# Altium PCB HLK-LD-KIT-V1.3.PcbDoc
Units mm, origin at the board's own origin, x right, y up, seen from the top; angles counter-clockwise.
Board outline 37.6 x 27.7 mm, 2 copper layers (Top Layer, Bottom Layer); 27 components, 16 nets, 94 pads, 84 vias.
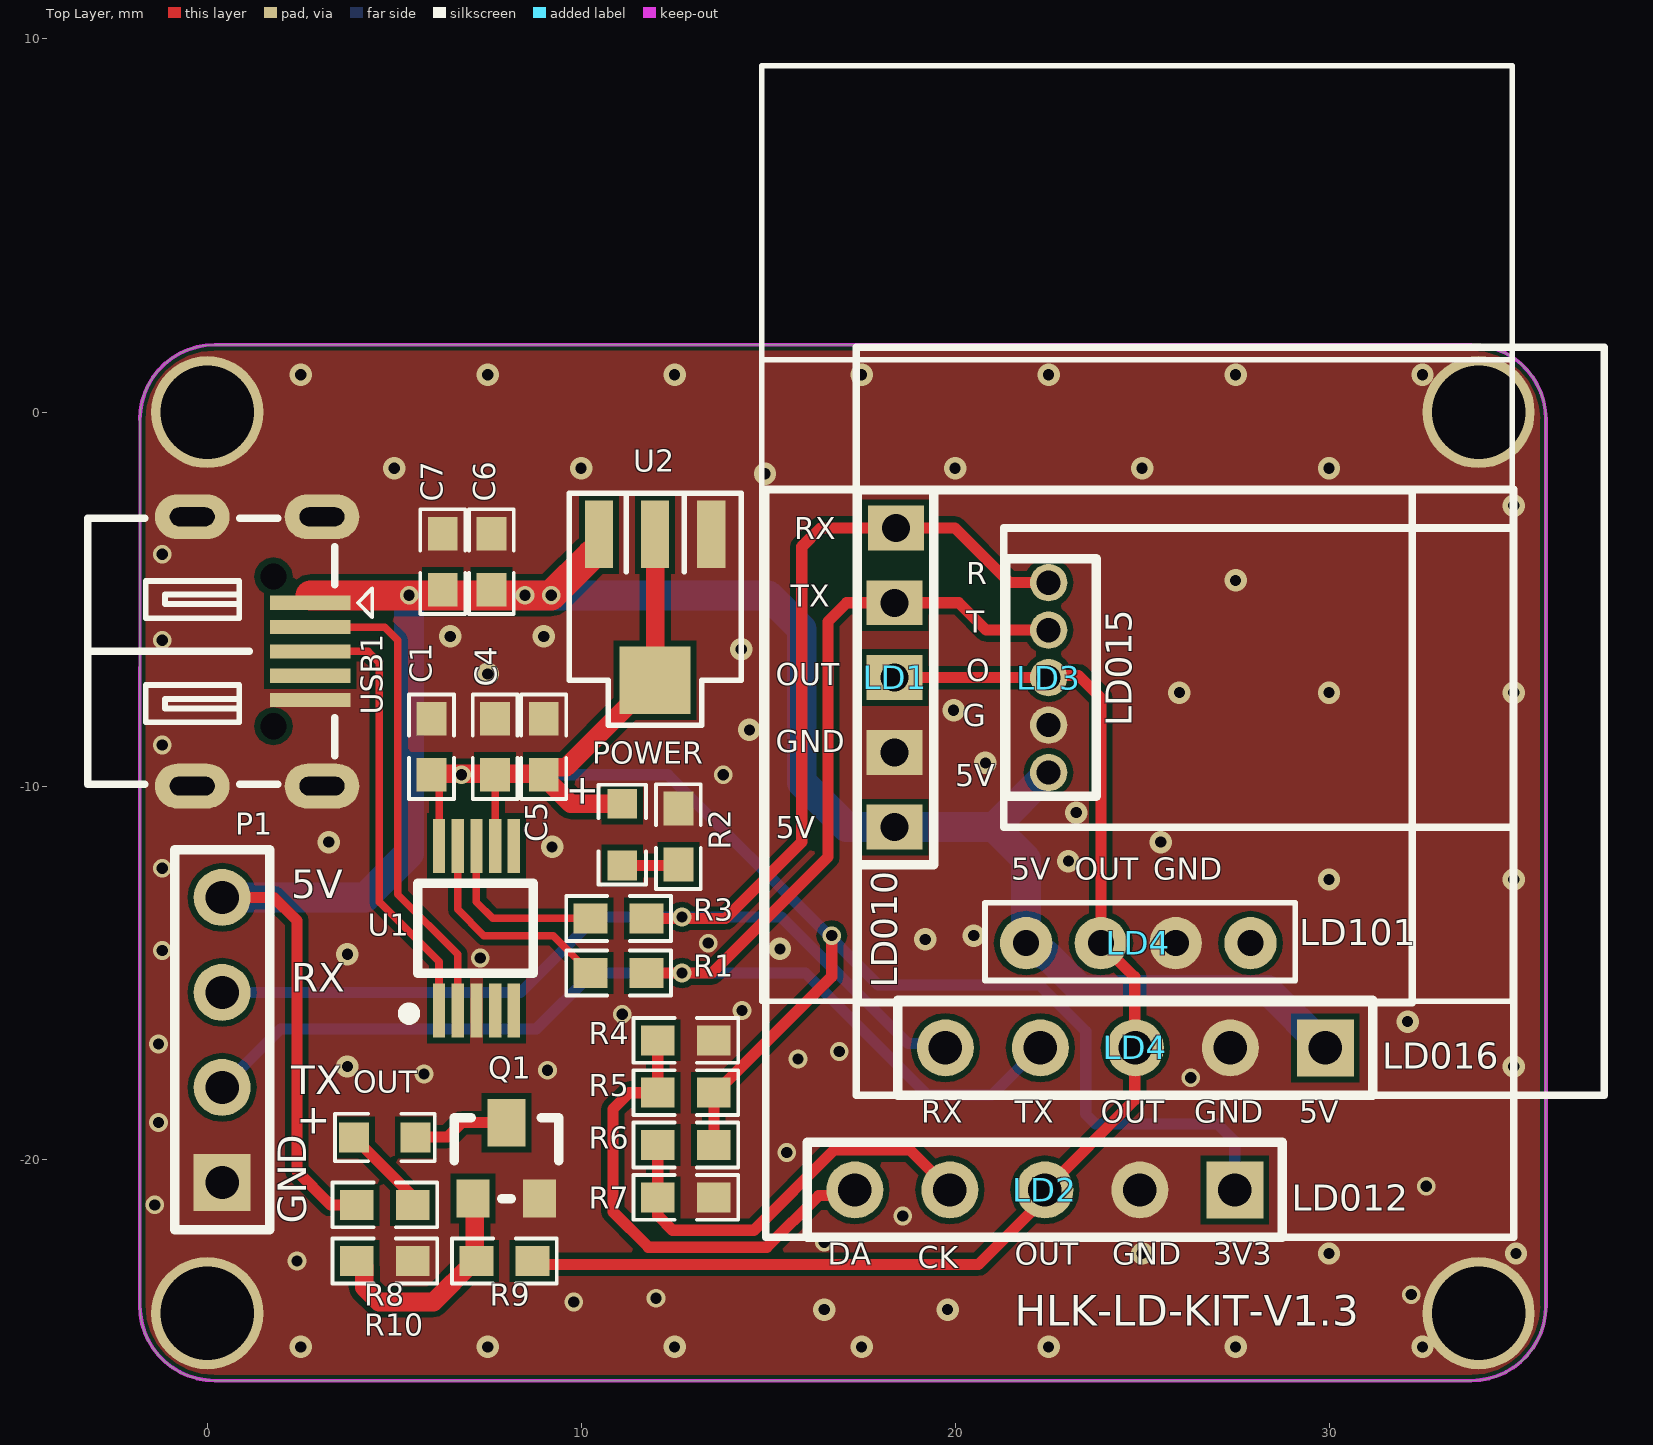
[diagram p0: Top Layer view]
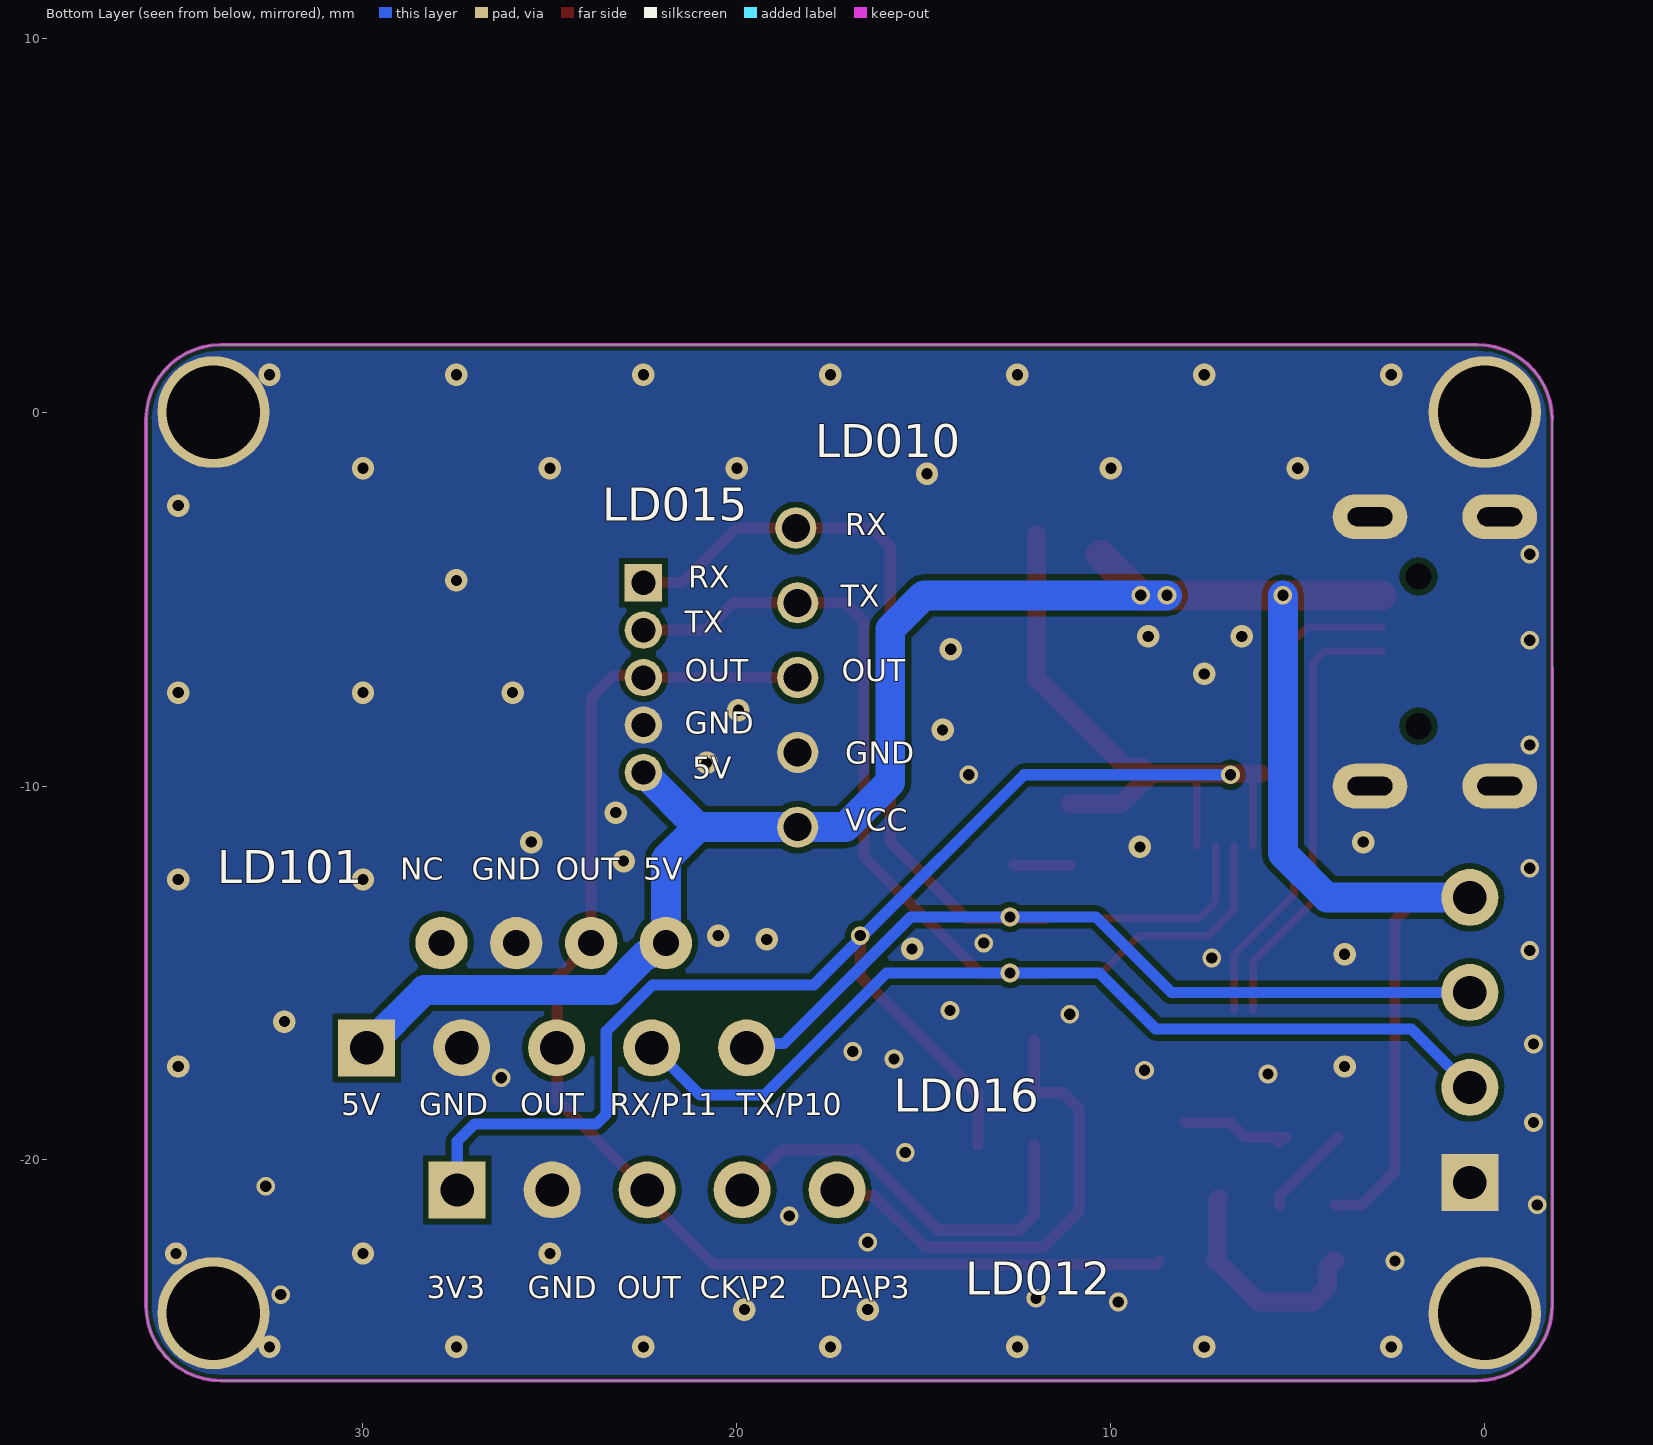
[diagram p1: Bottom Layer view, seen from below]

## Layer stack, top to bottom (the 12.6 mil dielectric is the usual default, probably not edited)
Top Solder: solder mask 0.0102, Solder Resist, Dk 3.5
Top Layer: signal copper 0.0356
Dielectric1: dielectric 0.32, FR-4, Dk 4.8
Bottom Layer: signal copper 0.0356
Bottom Solder: solder mask 0.0102, Solder Resist, Dk 3.5

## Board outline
-1.8,-23.9 -1.8,-0.2 cw(c0.2,-0.2) 0.2,1.8 33.8,1.8 cw(c33.8,-0.2) 35.8,-0.2 35.8,-23.9 cw(c33.8,-23.9) 33.8,-25.9 0.2,-25.9 cw(c0.2,-23.9)

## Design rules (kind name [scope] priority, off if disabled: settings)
Clearance Clearance_1 [OnLayer('Keep-Out Layer')] p1: gap=0.1 ignorepadtopadclearanceinfootprint=FALSE except(0: Arc-Hole Track-Hole SMDPad-Hole THPad-Hole Via-Hole Fill-Hole Poly-Hole Region-Hole Text-Hole)
Clearance [All] p2: gap=0.152 ignorepadtopadclearanceinfootprint=FALSE
FabricationTestPointUsage TestPointUsage [All] p1: valid=0 allowmultiple=FALSE
FabricationTestpoint Testpoint [(IsPad And (OnTopLayer Or OnBottomLayer))] p1: side=3 testpointundercomponent=TRUE minsize=1.016 maxsize=2.54 preferedsize=1.524 minholesize=0 maxholesize=1.016 preferedholesize=0.813 testpointgrid=0.025 allowsidetop=TRUE allowsidebottom=TRUE usegrid=TRUE gridtolerance=0
PolygonConnect [All] p1: connectstyle=Direct reliefconductorwidth=0.254 reliefentries=4 polygonreliefangle="90 Angle" airgapwidth=0.254
RoomDefinition HLK-LD-KIT-V1.3 [InComponentClass('HLK-LD-KIT-V1.3')] p1: confinementstyle=ConfineIn formatcopy=TRUE lockcomponents=FALSE outline -89.208,-91.397 -38.408,-91.397 -38.408,-65.997 -89.208,-65.997
RoutingVias [All] p1: holewidth=0.3 width=0.5 viastyle="Through Hole" minholewidth=0.3 minwidth=0.5 maxholewidth=0.711 maxwidth=1.27
SilkToSolderMaskClearance SilkscreenOverComponentPads [IsPad] p1: minsilkscreentomaskgap=0.254 clearancetoexposedcopper=TRUE
SolderMaskExpansion [All] p1: expansion=0.102 istentingtop=FALSE
Width 5V [InNet('5V')] p1: maxlimit=2 minlimit=0.3 preferedwidth=0.3
Width [All] p2: maxlimit=2 minlimit=0.2 preferedwidth=0.3
27 further rules are at their usual default settings.

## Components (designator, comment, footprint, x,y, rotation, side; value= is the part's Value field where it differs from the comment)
C1 "0.1uF" 0603 6,-8.95 r270 top
C4 "10uF" 0603 7.7,-8.95 r270 top value=100pF
C5 "0.1uF" 0603 9,-8.95 r270 top value=100pF
C6 "10uF" 0603 7.6,-4 r90 top value=100pF
C7 "0.1uF" 0603 6.3,-4 r90 top value=100pF
LD1 "HLK-LD010-5G" HLK-LD010-5G 18.4,-7.1 r0 top locked
LD2 "HLK-LD012-5G" HLK-LD012-5G 22.4,-20.8 r90 top locked
LD3 "HLK-LD015-5G" HLK-LD015-5G 22.5,-7.1 r0 top locked
LD4 "HLK-LD016" HLK-LD012-5G 24.82,-17 r90 top
LD4 "LD101" LD101插座 34.9,-4.2 r180 top (schematic designator U4)
OUT "" 0603LED 4.75,-19.4 r0 top
P1 "2.54*4单排插针" SIP_4P_2.54 0.4,-20.6 r90 top
POWER "LED" 0603LED 11.1,-11.3 r270 top
Q1 "3904" SOT-23 7.111,-21.032 r0 top
R1 "1K" 0603 11,-15 r180 top
R2 "1K" 0603 12.6,-11.35 r90 top
R3 "1K" 0603 11,-13.541 r180 top
R4 "NC/4.7K" 0603 12.8,-16.8 r0 top
R5 "NC/4.7K" 0603 12.8,-18.2 r0 top
R6 "NC/4.7K" 0603 12.8,-19.6 r0 top
R7 "NC/4.7K" 0603 12.8,-21 r0 top
R8 "1K" 0603 4.75,-21.2 r0 top
R9 "4.7K" 0603 7.95,-22.7 r0 top
R10 "47K" 0603 4.75,-22.7 r180 top
U1 "CH340E" MSOP-10 7.2,-13.8 r0 top
U2 "AMS1117" 1117 13.5,-3.2 r180 top
USB1 "micro usb" USB-MICRO_D -0.4,-6.4 r270 top

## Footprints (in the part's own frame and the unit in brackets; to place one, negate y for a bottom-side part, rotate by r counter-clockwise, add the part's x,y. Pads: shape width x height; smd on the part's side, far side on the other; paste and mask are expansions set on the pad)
0603 [mm]
  rect 0.9x0.8 smd: 1(-0.75,0) 2(0.75,0)
  silkscreen extent -1.4,-0.6 1.4,0.6
0603LED [mm]
  rect 0.8x0.8 smd: 1(-0.826,0) 2(0.826,0)
  silkscreen extent -1.33,-0.64 1.33,0.64
1117 [mm]
  rect 1.9x1.8 smd: 0(1.52,3.97)
  rect 0.75x1.8 smd: 1(0.02,0.07) 2(1.52,0.07) 3(3.02,0.07)
  silkscreen extent -0.78,-1.03 3.82,5.17, body extent -0.73,0.14 3.77,4.14, height 1.5
HLK-LD010-5G [mm]
  rect 1.5x1.2 / inner rrect0% 1.2x1.2 / far side round 1.1 hole 0.75: 1(0.025,4) 2(-0.025,2) 3(-0.025,0) 4(-0.025,-2) 5(-0.025,-4)
  silkscreen extent -0.99,-8.7 13.83,5
HLK-LD012-5G [mil]
  round 60 hole 35: 1(0,200) 2(0,100) 3(0,0) 4(0,-100)
  rect 60x60 / inner round 60 / far side rect 60x60 hole 35: 5(0,-200)
  silkscreen extent -50,-494 737,294
HLK-LD015-5G [mm]
  round 1 / inner round 1 / far side rect 1x1 hole 0.65: 1(0,2.54)
  round 1 hole 0.65: 2(0,1.27) 3(0,0) 4(0,-1.27) 5(0,-2.54)
  silkscreen extent -1.2,-4 12.4,4
LD101插座 [mm]
  round 1.4 hole 0.7: 1(13,10) 2(11,10) 3(9,10) 4(7,10)
  silkscreen extent 0,-13.46 20.07,11.56
MSOP-10 [mm]
  rect 0.33x1.45 smd: 1(-1,-2.2) 2(-0.5,-2.2) 3(0,-2.2) 4(0.5,-2.2) 5(1,-2.2) 6(1,2.2) 7(0.5,2.2) 8(0,2.2) 9(-0.5,2.2) 10(-1,2.2)
  silkscreen extent -1.95,-2.44 1.53,1.2
SIP_4P_2.54 [mil]
  rect 60x60 / inner round 60 / far side rect 60x60 hole 35: 1(0,0)
  round 60 hole 35: 2(100,0) 3(200,0) 4(300,0)
  silkscreen extent -50,-50 350,50
SOT-23 [mil]
  rect 35x40 smd: 1(0,0) 2(70,0)
  rect 40x50 smd: 3(35,80)
  silkscreen extent -20,0 90,85
USB-MICRO_D [mm] "micro型USB ，6.7*7.5*2.5mm"
  round 0 hole 0.7 unplated: 0(-2,2.17) 0(2,2.17)
  rect 0.381x2.15 smd: 1(-1.3,3.16) 2(-0.65,3.16) 3(0,3.16) 4(0.65,3.16) 5(1.3,3.16)
  oval 1.2x2 hole 0.5 slot 1.2 at 90 deg: 6(3.6,3.47) 7(3.6,0) 8(-3.6,0) 9(-3.6,3.47)
  silkscreen extent -3.56,-2.79 3.56,4.81

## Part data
C1: library part CAP, "Capacitor"
C4 C5 C6 C7: library part Cap, "Capacitor"
LD4: library part HLK-LD012-5G
OUT: library part LED
P1: library part 2.54*2插针
Q1: library part A09T, "NPN General Purpose Amplifier", PackageDocument=Sep-1998
R1 R2 R3 R4 R5 R6 R7 R8 R9 R10: library part Res1, "Resistor"
U2: library part Component_1
USB1: library part USB-D

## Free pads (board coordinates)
  round 3 hole 2.5: 0(0,-24.1) 0(34,0) 2(0,0) 2(34,-24.1)

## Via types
v1: diameter 0.6, hole 0.3, Top Layer to Bottom Layer, tented both sides, 51 vias
v2: diameter 0.5, hole 0.3, Top Layer to Bottom Layer, tented both sides, 33 vias

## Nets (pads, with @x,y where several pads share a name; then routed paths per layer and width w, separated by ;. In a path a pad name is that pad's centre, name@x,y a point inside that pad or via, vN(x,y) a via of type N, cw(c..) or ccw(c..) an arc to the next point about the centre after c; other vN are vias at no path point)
5V: C6.1 C7.1 LD1.5 LD3.5 LD4.1@21.9,-14.2 LD4.5 P1.4 R8.1 U2.3 USB1.1 | length 63.5
  Top Layer w0.3: P1.4 1.78,-12.98 2.4,-13.6 2.4,-20.3 3.3,-21.2 R8.1
  Top Layer w0.8: 2.76,-4.9 v2(5.4,-4.9) v2(8.5,-4.9) v2(9.2,-4.9) U2.3@10.275,-3.825
  Bottom Layer w0.8: P1.4 4.22,-12.98 5.4,-11.8 v2(5.4,-4.9) ; v2(8.5,-4.9) v2(9.2,-4.9) 15,-4.9 15.9,-5.8 15.9,-9.9 17.1,-11.1 LD1.5 21.04,-11.1 ; LD3.5 21.04,-11.1 ; LD4.5 28.352,-15.452 23.381,-15.452 22.429,-14.5 22.362,-14.5 22.062,-14.2 21.9,-14.2 21.9,-11.96 21.04,-11.1
DM: U1.2 USB1.2 | length 13
  Top Layer w0.2: USB1.2 4.75,-5.75 5.1,-6.1 5.1,-12.9 6.7,-14.5 U1.2
DP: U1.1 USB1.3 | length 11.9
  Top Layer w0.203: USB1.3 4.3,-6.4 4.6,-6.7 4.6,-13.1 6.2,-14.7 U1.1
GND: C1.1 C4.1 C5.1 C6.2 C7.2 LD1.4 LD2.4 LD3.4 LD4.3@25.9,-14.2 LD4.4@27.36,-17 P1.1 pad.0 pad.2 Q1.2 R2.2 R4.2 R7.2 R10.1 U1.3 U2.1 USB1.5 USB1.6 USB1.7 USB1.8 USB1.9
  other v1: 2.5,-25 7.5,-25 12.5,-25 17.5,-25 22.5,-25 27.5,-25 32.5,-25 16.5,-24 19.8,-24 25,-22.5 30,-22.5 35,-22.5 3.75,-17.5 34.94,-17.5 32.1,-16.3 3.75,-14.5 15.315,-14.355 19.2,-14.1 20.5,-14 30,-12.5 34.94,-12.5 23.031,-12.006 9.222,-11.627 3.25,-11.5 25.5,-11.5 23.24,-10.71 20.81,-9.381 14.5,-8.5 19.96,-7.972 26,-7.5 30,-7.5 34.94,-7.5 7.5,-7 14.28,-6.341 6.5,-6 9,-6 27.5,-4.5 34.94,-2.5 14.917,-1.65 5,-1.5 10,-1.5 20,-1.5 25,-1.5 30,-1.5 2.5,1 7.5,1 12.5,1 17.5,1 22.5,1 27.5,1 32.5,1
  other v2: 9.8,-23.8 12,-23.7 32.2,-23.6 2.4,-22.7 16.5,-22.2 18.6,-21.5 -1.4,-21.2 32.6,-20.7 15.5,-19.8 -1.3,-19 26.3,-17.8 5.8,-17.7 9.1,-17.6 15.8,-17.3 16.9,-17.1 -1.3,-16.9 11.1,-16.1 14.3,-16 7.3,-14.6 -1.2,-14.4 13.4,-14.2 -1.2,-12.2 13.8,-9.7 -1.2,-8.9 -1.2,-6.1 -1.2,-3.8
NetLD2_1: LD2.1 R4.1 R5.1 | length 13
  Top Layer w0.3: R4.1 R5.1 11.286,-18.2 10.85,-18.636 10.85,-21.384 11.798,-22.332 14.974,-22.332 16.356,-20.95 17.17,-20.95 LD2.1
NetLD2_2: LD2.2 R6.1 R7.1 | length 11.2
  Top Layer w0.3: R6.1 R7.1 12.05,-21.489 12.44,-21.879 14.621,-21.879 16.764,-19.736 18.796,-19.736 LD2.2
NetOUT_1: OUT.1 R8.2 | length 2.5
  Top Layer w0.3: OUT.1 5.5,-20.976 R8.2
NetOUT_2: OUT.2 Q1.3 | length 2.8
  Top Layer w0.3: OUT.2@5.336,-19.4 OUT.2@5.502,-19.4 ; OUT.2@5.502,-19.512 OUT.2@5.502,-19.474 ; OUT.2 5.592,-19.383 6.425,-19.383 6.809,-19 Q1.3
NetPOWER_2: POWER.2 R2.1 | length 1.5
  Top Layer w0.3: POWER.2 12.575,-12.126 R2.1
NetQ1_1: Q1.1 R9.1 R10.2 | length 6.1
  Top Layer w0.5: R10.2 4.05,-22.7 4.2,-22.85 4.2,-23.407 4.593,-23.8 6.05,-23.8 7.15,-22.7 R9.1 7.156,-22.655 7.156,-21.077 Q1.1
OUT: LD1.3 LD2.3 LD3.3 LD4.2@23.9,-14.2 LD4.3@24.82,-17 R9.2 | length 35
  Top Layer w0.3: R9.2 8.794,-22.794 20.625,-22.794 22.4,-21.019 LD2.3 24.802,-18.398 24.802,-15.102 23.9,-14.2 23.9,-7.647 23.298,-7.045 22.555,-7.045 LD3.3 LD1.3
RX: LD1.1 LD3.1 LD4.1@19.74,-17 P1.3 R3.1 | length 41.9
  Top Layer w0.3: R3.1 13.859,-13.541 15.9,-11.5 15.9,-3.6 16.4,-3.1 LD1.1 20,-3.1 21.46,-4.56 LD3.1
  Bottom Layer w0.3: P1.3 8.38,-15.52 10.4,-13.5 v2(12.7,-13.5) 15.352,-13.5 18.739,-16.887 19.627,-16.887 LD4.1@19.74,-17
RX0_CH340: R1.2 U1.9 | length 6
  Top Layer w0.2: U1.9 6.7,-12.4 6.7,-13.3 7.4,-14 9.25,-14 R1.2
TX: LD1.2 LD3.2 LD4.2@22.28,-17 P1.2 R1.1 | length 43.7
  Top Layer w0.3: R1.1 v2(12.7,-15) 13.5,-15 16.6,-11.9 16.6,-5.6 17.1,-5.1 LD1.2 20.1,-5.1 20.83,-5.83 LD3.2
  Bottom Layer w0.3: P1.2 1.96,-16.5 8.8,-16.5 10.3,-15 v2(12.7,-15) 16,-15 19.264,-18.264 20.986,-18.264 21.865,-17.385 LD4.2@21.865,-17
TX0_CH340: R3.2 U1.8 | length 4.7
  Top Layer w0.2: U1.8 7.2,-13.1 7.641,-13.541 R3.2
V3.3: C1.2 C4.2 C5.2 LD2.5 POWER.1 R5.2 R6.2 U1.7 U1.10 U2.0 U2.2 | length 51.5
  Top Layer w0.2: C1.2 6.2,-9.9 U1.10 ; U1.7 C4.2@7.7,-9.8
  Top Layer w0.3: C4.2 C4.2@7.75,-9.75 ; R6.2 R5.2 13.6,-18.2 16.7,-15.1 v2(16.7,-14)
  Top Layer w0.5: C1.2@6,-9.674 C5.2@9,-9.674 ; POWER.1 9.724,-10.475 9,-9.75 C5.2 C5.2@9,-9.674 ; U2.2 U2.0 11.93,-7.17 9.6,-9.5 9.15,-9.5 9,-9.65 C5.2@9,-9.674
  Bottom Layer w0.3: v2(6.8,-9.7) 12.322,-9.7 16.661,-14.039 17.946,-15.324 22.259,-15.324 23.492,-16.556 23.492,-18.772 23.756,-19.037 27.017,-19.037 27.48,-19.5 LD2.5
pads on no net: LD4.4@27.9,-14.2 U1.4 U1.5 U1.6 USB1.0 USB1.4

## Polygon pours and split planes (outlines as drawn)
GND on Top Layer "Keep-Out Layer-No Net" (solid, remove dead copper, pour order 1000): -2.1,2.2 -2.1,-26 -2.1,-26.6 36.8,-26.6 36.8,2 36.7,2.1 -2,2.1 -2.1,2.2
GND on Bottom Layer "Keep-Out Layer-No Net" (solid, remove dead copper, pour order 1001): -2.1,2.2 -2.1,-26 -2.1,-26.6 36.8,-26.6 36.8,2 36.7,2.1 -2,2.1 -2.1,2.2

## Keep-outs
Keep-Out Layer:
  lines w0.08: -1.8,-6.826 -1.8,-0.2
  lines w0.1: -1.8,-6.826 -1.8,-23.9 ccw(c0.2,-23.9) 0.2,-25.9 33.8,-25.9 ccw(c33.8,-23.9) 35.8,-23.9 35.8,-0.2 ccw(c33.8,-0.2) 33.8,1.8 0.2,1.8 ccw(c0.2,-0.2) -1.8,-0.2

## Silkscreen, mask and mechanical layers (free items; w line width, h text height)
Top Overlay:
  lines w0.15: 14.9,1.4 34.83,1.4 ; 20.8,-15.2 20.8,-13.122 29.1,-13.122 29.1,-15.2 20.8,-15.2
  text "RX" at 15.7,-3.6 h1
  text "R" at 20.3,-4.8 h1
  text "TX" at 15.6,-5.4 h1
  text "T" at 20.3,-6.1 h1
  text "O" at 20.3,-7.4 h1
  text "OUT" at 15.2,-7.5 h1
  text "G" at 20.2,-8.6 h1
  text "GND" at 15.2,-9.3 h1
  text "5V" at 20,-10.2 h1
  text "5V" at 15.2,-11.6 h1
  text "5V" at 21.5,-12.7 h1
  text "OUT" at 23.2,-12.7 h1
  text "GND" at 25.3,-12.7 h1
  text "5V" at 2.25,-13.25 h1.3
  text "LD101" at 29.2,-14.5 h1.2
  text "RX" at 2.25,-15.75 h1.3
  text "TX" at 2.25,-18.5 h1.3
  text "RX" at 19.1,-19.2 h1
  text "TX" at 21.6,-19.2 h1
  text "OUT" at 23.9,-19.2 h1
  text "GND" at 26.4,-19.2 h1
  text "5V" at 29.2,-19.2 h1
  text "GND" at 2.9,-21.7 h1.3 r90
  text "DA" at 16.6,-23 h1
  text "OUT" at 21.6,-23 h1
  text "GND" at 24.2,-23 h1
  text "3V3" at 26.9,-23 h1
  text "CK" at 19,-23.1 h1
  text "HLK-LD-KIT-V1.3" at 21.6,-24.7 h1.4
Bottom Overlay:
  text "LD010" at 17.9,-1.5 h1.5
  text "LD015" at 23.6,-3.2 h1.5
  text "5V" at 22.5,-12.7 h1
  text "OUT" at 24.849,-12.7 h1
  text "GND" at 27.092,-12.7 h1
  text "NC" at 29,-12.7 h1
  text "LD101" at 33.9,-12.9 h1.5
  text "LD016" at 15.8,-19 h1.5
  text "TX/P10" at 20,-19 h1
  text "RX/P11" at 23.4,-19 h1
  text "LD012" at 13.9,-23.9 h1.5
Top Solder:
  rectangle: 5.9,-12.5 8.5,-10.7
  rectangle: 5.9,-16.9 8.5,-15.1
